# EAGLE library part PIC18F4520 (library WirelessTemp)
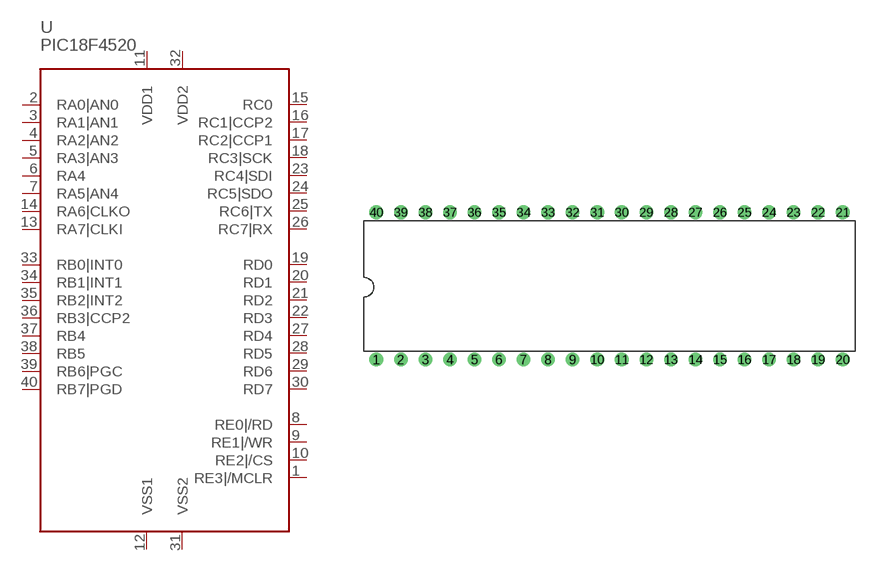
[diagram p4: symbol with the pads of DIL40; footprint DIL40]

Designator prefix U

## PIC18F4520-I/P  [DIL40]
1  RE3|/MCLR  in
2  RA0|AN0
3  RA1|AN1
4  RA2|AN2
5  RA3|AN3
6  RA4
7  RA5|AN4
8  RE0|/RD
9  RE1|/WR
10  RE2|/CS
11  VDD1  pwr
12  VSS1  pwr
13  RA7|CLKI
14  RA6|CLKO
15  RC0
16  RC1|CCP2
17  RC2|CCP1
18  RC3|SCK
19  RD0
20  RD1
21  RD2
22  RD3
23  RC4|SDI
24  RC5|SDO
25  RC6|TX
26  RC7|RX
27  RD4
28  RD5
29  RD6
30  RD7
31  VSS2  pwr
32  VDD2  pwr
33  RB0|INT0
34  RB1|INT1
35  RB2|INT2
36  RB3|CCP2
37  RB4
38  RB5
39  RB6|PGC
40  RB7|PGD

## Footprint DIL40 (pad centres in mm)
Dual In Line Package
drill 0.9 round: 1 -24.13,-7.62; 2 -21.59,-7.62; 3 -19.05,-7.62; 4 -16.51,-7.62; 5 -13.97,-7.62; 6 -11.43,-7.62; 7 -8.89,-7.62; 8 -6.35,-7.62; 9 -3.81,-7.62; 10 -1.27,-7.62; 11 1.27,-7.62; 12 3.81,-7.62; 13 6.35,-7.62; 14 8.89,-7.62; 15 11.43,-7.62; 16 13.97,-7.62; 17 16.51,-7.62; 18 19.05,-7.62; 19 21.59,-7.62; 20 24.13,-7.62; 21 24.13,7.62; 22 21.59,7.62; 23 19.05,7.62; 24 16.51,7.62; 25 13.97,7.62; 26 11.43,7.62; 27 8.89,7.62; 28 6.35,7.62; 29 3.81,7.62; 30 1.27,7.62; 31 -1.27,7.62; 32 -3.81,7.62; 33 -6.35,7.62; 34 -8.89,7.62; 35 -11.43,7.62; 36 -13.97,7.62; 37 -16.51,7.62; 38 -19.05,7.62; 39 -21.59,7.62; 40 -24.13,7.62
